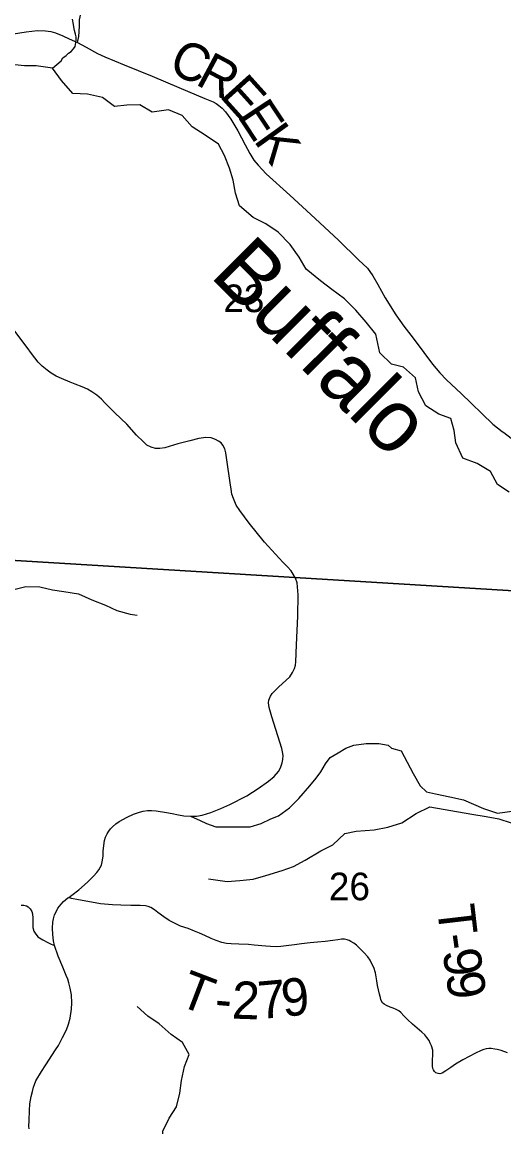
# Model space of a CAD drawing. Extents: x 0 to 45.4, y -2.2 to 22.
# Drawn here: x 7.301 to 8.031, y 16.232 to 17.906 of the extents above; entities that cross this region are included whole.
import ezdxf

# ---------------------------------------------------------------- set-up
doc = ezdxf.new("R2010")
doc.units = 0
for name, color, linetype in [('GM_X_Corporation', 7, 'Continuous'), ('GM_X_County_Road', 7, 'Continuous'), ('GM_X_County_Road_Text', 7, 'Continuous'), ('GM_X_Minor_River', 7, 'Continuous'), ('GM_X_Minor_River_Text', 7, 'Continuous'), ('GM_X_Section_Text', 7, 'Continuous'), ('GM_X_Township_Road', 7, 'Continuous'), ('GM_X_Township_Road_Text', 7, 'Continuous')]:
    doc.layers.add(name, color=color, linetype=linetype)

msp = doc.modelspace()

# ---------------------------------------------------------------- linework, layer by layer
at = {"layer": 'GM_X_Corporation'}
for points in [[(7.2262, 18.1039), (8.3245, 18.0384), (8.2701, 17.0306), (7.1661, 17.098)], [(8.2701, 17.0306), (8.2164, 16.0186), (7.1036, 16.0876), (7.1661, 17.098)]]:
    msp.add_lwpolyline(points, close=True, dxfattribs=at)
at = {"layer": 'GM_X_County_Road'}
for points in [[(7.2877, 17.8883), (7.3069, 17.8914), (7.3244, 17.8934), (7.3365, 17.8932), (7.3442, 17.8921), (7.3517, 17.8899), (7.3627, 17.8856), (7.3724, 17.8808), (7.3846, 17.8752), (7.3978, 17.8681), (7.415, 17.8587), (7.426, 17.8538), (7.4555, 17.8415), (7.4978, 17.8242), (7.5383, 17.8073), (7.578, 17.7905), (7.5902, 17.7853), (7.5952, 17.7828), (7.599, 17.7799), (7.6043, 17.7759), (7.6089, 17.7704), (7.6172, 17.7593), (7.6279, 17.7415), (7.639, 17.7201), (7.6461, 17.7072), (7.652, 17.6973), (7.6587, 17.6896), (7.671, 17.6764), (7.7064, 17.6442), (7.7448, 17.6088), (7.7802, 17.5758), (7.8107, 17.5463), (7.8241, 17.5336), (7.8323, 17.522), (7.8402, 17.5086), (7.851, 17.4883), (7.8671, 17.4628), (7.8795, 17.4455), (7.8938, 17.4274), (7.9099, 17.4056), (7.923, 17.3878), (7.934, 17.3746), (7.9441, 17.3642), (7.9661, 17.3433), (7.9813, 17.3287), (7.9982, 17.3127), (8.0142, 17.2971), (8.0286, 17.286)], [(7.6162, 17.2083), (7.6112, 17.2432), (7.6096, 17.2536), (7.6081, 17.2595), (7.6051, 17.2653), (7.6023, 17.2687), (7.5985, 17.2713), (7.5938, 17.2737), (7.5872, 17.2761), (7.5791, 17.277), (7.5687, 17.2751), (7.5553, 17.272), (7.5368, 17.2673), (7.5172, 17.2613), (7.5095, 17.2601), (7.5032, 17.2601), (7.4965, 17.262), (7.4901, 17.2654), (7.4849, 17.2701), (7.4744, 17.2805), (7.4594, 17.2968), (7.4416, 17.3142), (7.4264, 17.3296), (7.4214, 17.3349), (7.4139, 17.3409), (7.4065, 17.3459), (7.3998, 17.3501), (7.3919, 17.3534), (7.3812, 17.3577), (7.3738, 17.3609), (7.3605, 17.3664), (7.3523, 17.3698), (7.3449, 17.3743), (7.3386, 17.379), (7.331, 17.385), (7.3251, 17.3909), (7.3151, 17.4043), (7.3085, 17.4131), (7.2883, 17.4399)], [(8.0286, 17.286), (8.0309, 17.2842), (8.0421, 17.2756)], [(7.3501, 16.507), (7.3485, 16.5143), (7.3472, 16.5235), (7.3468, 16.5334), (7.3472, 16.5425), (7.3483, 16.5475), (7.3501, 16.5535), (7.3528, 16.5592), (7.3552, 16.5634), (7.3602, 16.5698), (7.3637, 16.5735), (7.3701, 16.5791), (7.3715, 16.5799), (7.376, 16.5832), (7.3868, 16.5913), (7.4, 16.6032), (7.409, 16.612), (7.414, 16.6177), (7.4171, 16.6216), (7.4192, 16.6251), (7.421, 16.6289), (7.4224, 16.6339), (7.4236, 16.6422), (7.4238, 16.6501), (7.4246, 16.6585), (7.4257, 16.6662), (7.4272, 16.671), (7.4298, 16.6762), (7.4325, 16.6804), (7.4348, 16.6838), (7.4378, 16.6869), (7.4429, 16.6916), (7.448, 16.695), (7.4599, 16.7015), (7.4699, 16.7058), (7.4789, 16.709), (7.4845, 16.7106), (7.4911, 16.7116), (7.497, 16.7117), (7.5042, 16.7109), (7.5199, 16.7087), (7.5284, 16.7069), (7.5377, 16.7049), (7.5458, 16.7033), (7.5559, 16.7028), (7.5651, 16.7031), (7.574, 16.7046), (7.587, 16.7087), (7.6019, 16.7146), (7.6157, 16.7206), (7.6412, 16.7338), (7.6585, 16.7449), (7.6741, 16.7563), (7.6827, 16.7632), (7.6892, 16.7705), (7.6922, 16.7751), (7.6932, 16.778), (7.695, 16.7836), (7.6961, 16.7891), (7.6963, 16.7947), (7.6955, 16.8007), (7.6944, 16.8057), (7.6794, 16.8534), (7.6751, 16.8679), (7.6745, 16.8747), (7.675, 16.8787), (7.6758, 16.8815), (7.6772, 16.885), (7.6796, 16.8888), (7.6899, 16.8989), (7.7006, 16.9085), (7.7064, 16.9144), (7.7107, 16.9209), (7.7136, 16.9266), (7.7151, 16.9317), (7.7157, 16.9367), (7.7169, 16.9625), (7.719, 17.0063), (7.7193, 17.0384), (7.7176, 17.0566), (7.7151, 17.0637), (7.7119, 17.0697), (7.7085, 17.0748), (7.7031, 17.081), (7.6962, 17.0879), (7.668, 17.1184), (7.6451, 17.1469), (7.631, 17.1661), (7.6255, 17.1744), (7.621, 17.1845), (7.6188, 17.1911), (7.6176, 17.1983), (7.6162, 17.2083)], [(7.2994, 16.5679), (7.3037, 16.5679), (7.3073, 16.5669), (7.3101, 16.5654), (7.3132, 16.5626), (7.3156, 16.5583), (7.3164, 16.5551), (7.3171, 16.5483), (7.3169, 16.5442), (7.317, 16.538), (7.3173, 16.5341), (7.3187, 16.5287), (7.3204, 16.5255), (7.3245, 16.5202), (7.3274, 16.5184), (7.3322, 16.5155), (7.3396, 16.5118), (7.3447, 16.5092), (7.3501, 16.507)], [(7.3117, 16.2292), (7.3111, 16.2332), (7.3115, 16.2417), (7.312, 16.2568), (7.3128, 16.2669), (7.3144, 16.2781), (7.3164, 16.2859), (7.3182, 16.2923), (7.3194, 16.2963), (7.3218, 16.302), (7.3302, 16.3162), (7.3368, 16.3262), (7.3517, 16.3487), (7.3558, 16.3555), (7.3623, 16.3676), (7.3683, 16.3794), (7.3711, 16.3879), (7.3736, 16.3971), (7.3758, 16.4105), (7.3764, 16.4204), (7.3757, 16.4322), (7.3738, 16.4424), (7.3717, 16.4503), (7.3699, 16.4559), (7.3676, 16.4615), (7.3625, 16.4744), (7.3556, 16.4908), (7.3501, 16.507)]]:
    msp.add_lwpolyline(points, dxfattribs=at)
at = {"layer": 'GM_X_Minor_River'}
for points in [[(7.347, 17.8363), (7.36, 17.8475), (7.3628, 17.852), (7.3674, 17.8557), (7.3712, 17.8594), (7.3751, 17.862), (7.3789, 17.8658), (7.3812, 17.8691), (7.3825, 17.8756), (7.383, 17.8801), (7.3826, 17.8839), (7.3816, 17.8881), (7.3802, 17.8935), (7.3791, 17.8992), (7.3788, 17.9026), (7.3774, 17.911)], [(7.322, 17.8401), (7.3046, 17.8402), (7.2804, 17.8426)], [(8.0389, 17.1942), (8.0215, 17.2056), (8.011, 17.2254), (7.9906, 17.2376), (7.9686, 17.2453), (7.9581, 17.2689), (7.9559, 17.2872), (7.9507, 17.3054), (7.9325, 17.3123), (7.9129, 17.3246), (7.9016, 17.3459), (7.8972, 17.3672), (7.8791, 17.3832), (7.8609, 17.3878), (7.8428, 17.4053), (7.8369, 17.4335), (7.8225, 17.4518), (7.8067, 17.47), (7.7894, 17.4868), (7.7705, 17.5013), (7.7531, 17.5143), (7.7312, 17.5319), (7.7207, 17.5501), (7.7072, 17.5692), (7.6891, 17.5882), (7.6702, 17.6004), (7.6513, 17.6104), (7.6302, 17.6279), (7.6242, 17.6469), (7.6205, 17.6667), (7.6152, 17.6849), (7.6077, 17.704), (7.5987, 17.7215), (7.5783, 17.7352), (7.5587, 17.7474), (7.5436, 17.7649), (7.5225, 17.7734), (7.4982, 17.7697), (7.4793, 17.7811), (7.4596, 17.7804), (7.4407, 17.7782), (7.4226, 17.7919), (7.3999, 17.7973), (7.3779, 17.7982), (7.3606, 17.818), (7.347, 17.8363), (7.322, 17.8401)], [(7.2885, 17.0463), (7.3067, 17.0508), (7.3279, 17.0507), (7.3468, 17.0461), (7.3642, 17.0437), (7.3862, 17.0399), (7.4066, 17.0307), (7.427, 17.023), (7.4444, 17.0146), (7.4648, 17.0092), (7.4754, 17.0076)], [(7.5836, 16.608), (7.6116, 16.6041), (7.6306, 16.6055), (7.651, 16.6077), (7.67, 16.613), (7.695, 16.6205), (7.7124, 16.6265), (7.7299, 16.6364), (7.7534, 16.6507), (7.7717, 16.6598), (7.7899, 16.6765), (7.8073, 16.6802), (7.8346, 16.6824), (7.8551, 16.6861), (7.8763, 16.6929), (7.8983, 16.7073), (7.9188, 16.7171), (7.9824, 16.7062), (8.0043, 16.7023), (8.0232, 16.6992), (8.0422, 16.693)], [(7.5145, 16.1739), (7.5139, 16.199), (7.514, 16.2256), (7.5239, 16.2453), (7.5346, 16.2628), (7.5399, 16.2833), (7.5423, 16.3023), (7.5469, 16.3236), (7.5538, 16.3418), (7.544, 16.3601), (7.5267, 16.3724), (7.5085, 16.3884), (7.4912, 16.3999), (7.4753, 16.4144)]]:
    msp.add_lwpolyline(points, dxfattribs=at)
at = {"layer": 'GM_X_Township_Road'}
for points in [[(7.3846, 17.8752), (7.3867, 17.8843), (7.3877, 17.9003), (7.3878, 17.9099), (7.3959, 17.9466), (7.3994, 17.9753), (7.3993, 17.9828), (7.3992, 17.9907), (7.3994, 18.0003), (7.4005, 18.0059), (7.4024, 18.0124), (7.403, 18.0142)], [(7.5559, 16.7028), (7.5707, 16.6965), (7.5802, 16.6918), (7.5945, 16.687), (7.6467, 16.687), (7.6634, 16.6918), (7.6776, 16.6989), (7.6895, 16.7037), (7.7061, 16.7156), (7.7193, 16.7288), (7.7204, 16.7299), (7.737, 16.7489), (7.7465, 16.7608), (7.7536, 16.7703), (7.7607, 16.7822), (7.7679, 16.7917), (7.7797, 16.7989), (7.7916, 16.806), (7.8035, 16.8108), (7.8225, 16.8132), (7.8331, 16.8132)], [(7.8331, 16.8132), (7.8415, 16.8132), (7.8558, 16.8108), (7.8605, 16.806), (7.8754, 16.8018), (7.8935, 16.7679), (7.9042, 16.7489), (7.9136, 16.7398), (7.9276, 16.7367), (7.9492, 16.7322), (7.9697, 16.728), (8, 16.7147), (8.0212, 16.7078), (8.0471, 16.7112), (8.0591, 16.7006), (8.0848, 16.7005), (8.1565, 16.7093), (8.1615, 16.7099)], [(7.8434, 16.4299), (7.8424, 16.4334), (7.8395, 16.4464), (7.8386, 16.4535), (7.8364, 16.4654), (7.8338, 16.4738), (7.8306, 16.4803), (7.8283, 16.4848), (7.8248, 16.4898), (7.8195, 16.496), (7.8134, 16.5021), (7.8076, 16.5077), (7.8038, 16.5107), (7.7993, 16.5133), (7.7967, 16.5147), (7.7935, 16.5158), (7.7896, 16.5165), (7.785, 16.5164), (7.7794, 16.5156), (7.772, 16.5147), (7.7604, 16.5129), (7.7486, 16.5119), (7.7374, 16.5111), (7.7242, 16.5098), (7.7138, 16.5081), (7.7013, 16.5066), (7.6928, 16.5057), (7.6871, 16.5051), (7.6773, 16.5053), (7.6702, 16.5062), (7.6525, 16.5076), (7.6438, 16.5083), (7.6292, 16.5092), (7.6179, 16.5094), (7.6107, 16.5103), (7.6034, 16.5115), (7.5948, 16.5144), (7.5873, 16.5177), (7.5776, 16.5223), (7.5695, 16.5256), (7.5623, 16.529), (7.5524, 16.5328), (7.5411, 16.5365), (7.5316, 16.5407), (7.5236, 16.5448), (7.5157, 16.5503), (7.5067, 16.5572), (7.5015, 16.5611), (7.4962, 16.5645), (7.492, 16.5662), (7.488, 16.5672), (7.4798, 16.5674), (7.4658, 16.5678), (7.4505, 16.5679), (7.4378, 16.5685), (7.4198, 16.57), (7.4062, 16.5729), (7.3865, 16.5761), (7.3758, 16.578), (7.3715, 16.5799)], [(8.0365, 16.3444), (8.0271, 16.3477), (8.021, 16.3495), (8.0175, 16.35), (8.0118, 16.3508), (8.008, 16.3508), (8.0041, 16.3504), (8.0007, 16.3496), (7.9965, 16.348), (7.988, 16.344), (7.9785, 16.339), (7.9688, 16.3336), (7.9577, 16.327), (7.9508, 16.3223), (7.9431, 16.3172), (7.9377, 16.3138), (7.9339, 16.3127), (7.9312, 16.313), (7.9281, 16.3142), (7.9257, 16.3161), (7.9244, 16.3185), (7.9234, 16.3208), (7.9227, 16.324), (7.9228, 16.3303), (7.923, 16.3353), (7.9233, 16.3394), (7.9233, 16.3439), (7.9232, 16.3482), (7.9211, 16.3549), (7.9195, 16.359), (7.9177, 16.363), (7.9145, 16.3677), (7.9114, 16.3715), (7.9065, 16.3758), (7.8995, 16.3818), (7.8925, 16.3878), (7.8848, 16.3949), (7.8796, 16.4007), (7.8749, 16.4056), (7.872, 16.408), (7.8677, 16.4102), (7.8632, 16.4121), (7.8587, 16.4138), (7.853, 16.4162), (7.8498, 16.4181), (7.8473, 16.4204), (7.8448, 16.4245), (7.844, 16.4282), (7.8434, 16.4299)]]:
    msp.add_lwpolyline(points, dxfattribs=at)

# ---------------------------------------------------------------- texts
at = {"layer": 'GM_X_County_Road_Text'}
for s, rotation, p in [('C', 335.1199, (7.5202, 17.8321)), ('R', 331.8333, (7.5618, 17.8128)), ('E', 312.0311, (7.5989, 17.794)), ('E', 303.4892, (7.626, 17.7642)), ('K', 305.6897, (7.6508, 17.7268))]:
    msp.add_text(s, height=0.0568, rotation=rotation, dxfattribs=at).set_placement(p)
at = {"layer": 'GM_X_Minor_River_Text'}
msp.add_text('Buffalo', height=0.09471, rotation=314.8733, dxfattribs=at).set_placement((7.5838, 17.5216))
at = {"layer": 'GM_X_Section_Text'}
for s, p in [('23', (7.6058, 17.4668)), ('26', (7.7658, 16.5756))]:
    msp.add_text(s, height=0.04186, rotation=0, dxfattribs=at).set_placement(p)
at = {"layer": 'GM_X_Township_Road_Text'}
for s, rotation, p in [('T', 276.6663, (7.9295, 16.566)), ('-', 277.9144, (7.9346, 16.5225)), ('9', 278.4253, (7.9379, 16.4988)), ('T', 339.0432, (7.535, 16.4176)), ('9', 6.2418, (7.6967, 16.3987)), ('9', 277.9249, (7.943, 16.4643)), ('2', 358.1514, (7.6181, 16.3963)), ('7', 5.1509, (7.6607, 16.3954)), ('-', 355.0542, (7.5915, 16.3985))]:
    msp.add_text(s, height=0.0568, rotation=rotation, dxfattribs=at).set_placement(p)

doc.saveas('drawing.dxf')
